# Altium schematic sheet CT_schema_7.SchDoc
size 287 x 160 mm
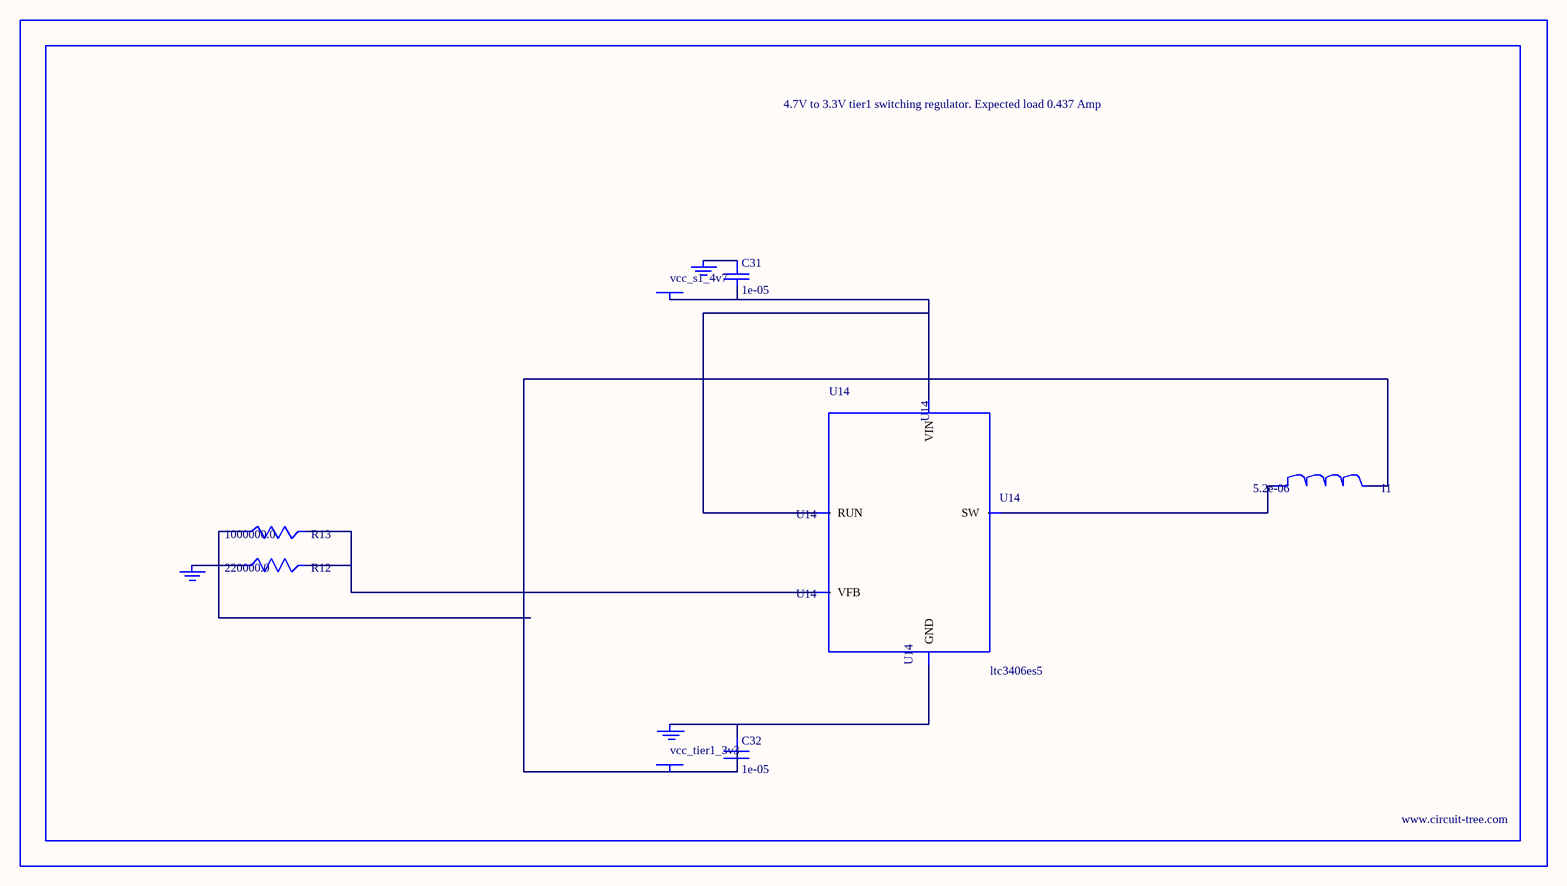
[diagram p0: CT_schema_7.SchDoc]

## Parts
BORDER6  (no value)
C31  1e-05  [C0805]
C32  1e-05  [C0805]
GND_INSTANCE_6_0  (no value)
GND_INSTANCE_6_1  (no value)
GND_INSTANCE_6_2  (no value)
I1  5.2e-06  [DR1040]
POWER_INSTANCE_6_0  vcc_tier1_3v3
POWER_INSTANCE_6_1  vcc_s1_4v7
R12  220000.0  [R0603]
R13  1000000.0  [R0603]
U14  ltc3406es5  [TSOT-23-5]

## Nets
NetC31_1: C31.1 GND_INSTANCE_6_1.0(GND)
NetC31_2: C31.2 POWER_INSTANCE_6_1.0(PWR) U14.1(RUN) U14.4(VIN)
NetC32_1: C32.1 GND_INSTANCE_6_0.0(GND) U14.2(GND)
NetC32_2: C32.2 I1.2 POWER_INSTANCE_6_0.0(PWR) R13.1
NetGND_INSTANCE_6_2_0: GND_INSTANCE_6_2.0(GND) R12.1
NetI1_1: I1.1 U14.3(SW)
NetR12_2: R12.2 R13.2 U14.5(VFB)

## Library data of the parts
BORDER6 = BORDER_PAGE6
C31 C32 = C0805C106K8RACTU
GND_INSTANCE_6_0-GND_INSTANCE_6_2 = GND
I1 = DR1040-5R2-R
POWER_INSTANCE_6_0 POWER_INSTANCE_6_1 = PWR
R12 = RC0603JR-07220KL
R13 = RC0603JR-071ML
